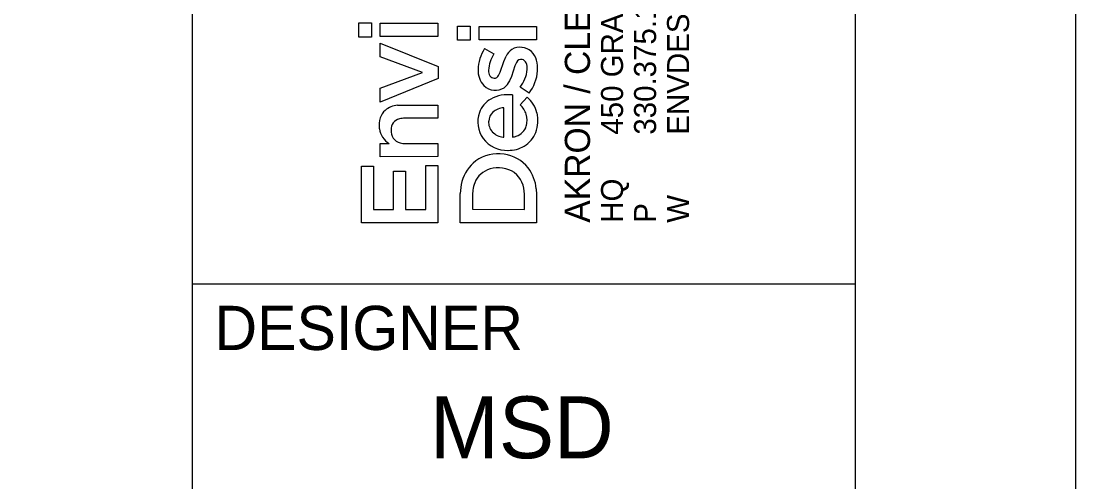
# Model space of a CAD drawing. Extents: x -4.2 to 34, y 0 to 22.
# Drawn here: x 31.612 to 34, y 2.552 to 3.594 of the extents above; entities that cross this region are included whole.
import ezdxf

# ---------------------------------------------------------------- set-up
doc = ezdxf.new("R2010")
doc.units = 0
for name, color, linetype in [('SH_Border', 7, 'Continuous'), ('SH_Cut_Line', 7, 'Continuous'), ('SH_Data', 7, 'Continuous')]:
    doc.layers.add(name, color=color, linetype=linetype)

msp = doc.modelspace()

# ---------------------------------------------------------------- linework, layer by layer
at = {"layer": 'SH_Border'}
for p, q in [((32, 0.5), (32, 21.5)), ((32, 3), (33.5, 3))]:
    msp.add_line(p, q, dxfattribs=at)
msp.add_lwpolyline([(1.5, 21.5), (33.5, 21.5), (33.5, 0.5), (1.5, 0.5)], close=True, dxfattribs=at)
at = {"layer": 'SH_Cut_Line'}
msp.add_lwpolyline([(0, 0), (34, 0), (34, 22), (0, 22)], close=True, dxfattribs=at)
at = {"layer": 'SH_Data'}
for p, q in [((32.3771, 3.5582), (32.3771, 3.5903)), ((32.3771, 3.5903), (32.4054, 3.5903)), ((32.4054, 3.5903), (32.4054, 3.5582)), ((32.4254, 3.5594), (32.4254, 3.5893)), ((32.4254, 3.5893), (32.5557, 3.5893)), ((32.5557, 3.5893), (32.5557, 3.5594)), ((32.6005, 3.5511), (32.6005, 3.5832)), ((32.6005, 3.5832), (32.6289, 3.5832)), ((32.6289, 3.5832), (32.6289, 3.5511)), ((32.6489, 3.5523), (32.6489, 3.5822)), ((32.6489, 3.5822), (32.7792, 3.5822)), ((32.7792, 3.5822), (32.7792, 3.5523)), ((32.4054, 3.5582), (32.3771, 3.5582)), ((32.5557, 3.5594), (32.4254, 3.5594)), ((32.4254, 3.5133), (32.4254, 3.5446)), ((32.4254, 3.5446), (32.5567, 3.4913)), ((32.6289, 3.5511), (32.6005, 3.5511)), ((32.7792, 3.5523), (32.6489, 3.5523)), ((32.5212, 3.478), (32.4254, 3.5133)), ((32.6615, 3.5321), (32.6827, 3.5203)), ((32.7048, 3.5026), (32.7104, 3.5153)), ((32.5567, 3.4913), (32.5567, 3.4644)), ((32.6967, 3.4787), (32.7048, 3.5026)), ((32.7298, 3.4933), (32.7221, 3.4688)), ((32.7334, 3.501), (32.7298, 3.4933)), ((32.4254, 3.4429), (32.5212, 3.478)), ((32.5567, 3.4644), (32.4254, 3.4109)), ((32.693, 3.4712), (32.6967, 3.4787)), ((32.7221, 3.4688), (32.7182, 3.4592)), ((32.4254, 3.4109), (32.4254, 3.4429)), ((32.7621, 3.4314), (32.742, 3.4447)), ((32.7245, 3.4275), (32.7246, 3.3319)), ((32.7423, 3.4046), (32.7577, 3.422)), ((32.4644, 3.404), (32.4729, 3.4044)), ((32.4729, 3.4044), (32.5557, 3.4044)), ((32.5557, 3.4044), (32.5557, 3.3746)), ((32.7049, 3.3318), (32.7049, 3.3983)), ((32.5557, 3.3746), (32.4814, 3.3746)), ((32.7036, 3.3317), (32.7049, 3.3318)), ((32.4254, 3.2875), (32.4254, 3.3173)), ((32.4254, 3.3173), (32.4455, 3.3173)), ((32.4822, 3.3173), (32.5557, 3.3173)), ((32.5557, 3.3173), (32.5557, 3.2876)), ((32.5557, 3.2876), (32.4254, 3.2875)), ((32.383, 3.1379), (32.383, 3.266)), ((32.383, 3.266), (32.4101, 3.266)), ((32.4101, 3.266), (32.4101, 3.1683)), ((32.455, 3.1683), (32.455, 3.2549)), ((32.455, 3.2549), (32.4822, 3.2549)), ((32.4822, 3.2549), (32.4822, 3.1683)), ((32.5286, 3.1683), (32.5286, 3.2672)), ((32.5286, 3.2672), (32.5557, 3.2672)), ((32.5557, 3.2672), (32.5557, 3.1379)), ((32.6064, 3.138), (32.6064, 3.204)), ((32.6347, 3.2118), (32.6341, 3.2023)), ((32.6341, 3.2023), (32.6341, 3.1684)), ((32.7515, 3.1683), (32.7515, 3.2024)), ((32.7785, 3.215), (32.7792, 3.2021)), ((32.7792, 3.2021), (32.7792, 3.138)), ((32.4101, 3.1683), (32.455, 3.1683)), ((32.4822, 3.1683), (32.5286, 3.1683)), ((32.6341, 3.1684), (32.7515, 3.1683)), ((32.5557, 3.1379), (32.383, 3.1379)), ((32.7792, 3.138), (32.6064, 3.138))]:
    msp.add_line(p, q, dxfattribs=at)
for points in [[(32.3771, 3.5582), (32.3771, 3.5903), (32.4054, 3.5903), (32.4054, 3.5582)], [(32.4254, 3.5594), (32.4254, 3.5893), (32.5557, 3.5893), (32.5557, 3.5594)], [(32.6005, 3.5511), (32.6005, 3.5832), (32.6289, 3.5832), (32.6289, 3.5511)], [(32.6489, 3.5523), (32.6489, 3.5822), (32.7792, 3.5822), (32.7792, 3.5523)], [(32.4254, 3.4109), (32.4254, 3.4429), (32.5212, 3.478), (32.4254, 3.5133), (32.4254, 3.5446), (32.5567, 3.4913), (32.5567, 3.4644)], [(32.383, 3.1379), (32.383, 3.266), (32.4101, 3.266), (32.4101, 3.1683), (32.455, 3.1683), (32.455, 3.2549), (32.4822, 3.2549), (32.4822, 3.1683), (32.5286, 3.1683), (32.5286, 3.2672), (32.5557, 3.2672), (32.5557, 3.1379)]]:
    msp.add_lwpolyline(points, close=True, dxfattribs=at)
for points in [[(32.6615, 3.5321), (32.6827, 3.5203)], [(32.693, 3.4712), (32.6967, 3.4787), (32.7048, 3.5026), (32.7104, 3.5153)], [(32.7334, 3.501), (32.7298, 3.4933), (32.7221, 3.4688), (32.7182, 3.4592)], [(32.7621, 3.4314), (32.742, 3.4447)], [(32.7245, 3.4275), (32.7246, 3.3319)], [(32.7423, 3.4046), (32.7577, 3.422)], [(32.4644, 3.404), (32.4729, 3.4044), (32.5557, 3.4044), (32.5557, 3.3746), (32.4814, 3.3746)], [(32.7036, 3.3317), (32.7049, 3.3318), (32.7049, 3.3983)], [(32.4254, 3.2875), (32.4254, 3.3173), (32.4455, 3.3173)], [(32.4822, 3.3173), (32.5557, 3.3173), (32.5557, 3.2876), (32.4254, 3.2875)], [(32.7785, 3.215), (32.7792, 3.2021), (32.7792, 3.138), (32.6064, 3.138)], [(32.6064, 3.138), (32.6064, 3.204)], [(32.6347, 3.2118), (32.6341, 3.2023), (32.6341, 3.1684), (32.7515, 3.1683), (32.7515, 3.2024)]]:
    msp.add_lwpolyline(points, dxfattribs=at)
for centre, radius, start, end in [((32.7406, 3.5026), 0.0326, 80.1719, 122.5197), ((32.7406, 3.5026), 0.0326, 80.1719, 122.5197), ((32.7428, 3.4982), 0.0367, 47.7934, 84.6892), ((32.7428, 3.4982), 0.0367, 47.7934, 84.6892), ((32.7364, 3.4826), 0.0897, 146.531, 178.7571), ((32.7364, 3.4826), 0.0897, 146.531, 178.7571), ((32.7452, 3.4789), 0.0749, 146.5112, 176.9101), ((32.7452, 3.4789), 0.0749, 146.5112, 176.9101), ((32.7466, 3.4971), 0.0405, 125.5118, 153.4159), ((32.7466, 3.4971), 0.0405, 125.5118, 153.4159), ((32.7379, 3.4946), 0.0427, 14.9966, 46.2063), ((32.7379, 3.4946), 0.0427, 14.9966, 46.2063), ((32.7438, 3.4963), 0.0114, 76.6609, 155.7053), ((32.7438, 3.4963), 0.0114, 76.6609, 155.7053), ((32.744, 3.4951), 0.0126, 21.5098, 78.5262), ((32.744, 3.4951), 0.0126, 21.5098, 78.5262), ((32.7259, 3.4877), 0.0321, 354.5726, 22.068), ((32.7259, 3.4877), 0.0321, 354.5726, 22.068), ((32.7104, 3.4867), 0.0712, 355.8306, 15.3914), ((32.7104, 3.4867), 0.0712, 355.8306, 15.3914), ((32.6967, 3.4824), 0.0501, 177.5366, 222.7932), ((32.6967, 3.4824), 0.0501, 177.5366, 222.7932), ((32.6931, 3.4823), 0.0228, 178.4747, 211.0868), ((32.6931, 3.4823), 0.0228, 178.4747, 211.0868), ((32.6833, 3.4767), 0.0115, 212.2368, 268.3777), ((32.6833, 3.4767), 0.0115, 212.2368, 268.3777), ((32.6834, 3.4759), 0.0107, 267.716, 333.7337), ((32.6834, 3.4759), 0.0107, 267.716, 333.7337), ((32.6825, 3.4915), 0.0757, 321.811, 354.7969), ((32.6825, 3.4915), 0.0757, 321.811, 354.7969), ((32.6895, 3.4882), 0.0922, 321.9777, 355.8738), ((32.6895, 3.4882), 0.0922, 321.9777, 355.8738), ((32.686, 3.4753), 0.0375, 225.9854, 302.4797), ((32.686, 3.4753), 0.0375, 225.9854, 302.4797), ((32.681, 3.4758), 0.0408, 308.0877, 335.9874), ((32.681, 3.4758), 0.0408, 308.0877, 335.9874), ((32.7024, 3.3691), 0.0558, 118.8308, 160.6244), ((32.7024, 3.3691), 0.0558, 118.8308, 160.6244), ((32.7152, 3.3441), 0.0838, 83.615, 118.2876), ((32.7152, 3.3441), 0.0838, 83.615, 118.2876), ((32.7174, 3.3717), 0.0644, 13.5336, 51.3615), ((32.7174, 3.3717), 0.0644, 13.5336, 51.3615), ((32.4635, 3.3626), 0.0402, 132.2219, 161.6818), ((32.4635, 3.3626), 0.0402, 132.2219, 161.6818), ((32.4687, 3.3543), 0.0499, 94.9696, 130.2225), ((32.4687, 3.3543), 0.0499, 94.9696, 130.2225), ((32.7079, 3.3561), 0.0424, 94.008, 130.8817), ((32.7079, 3.3561), 0.0424, 94.008, 130.8817), ((32.7038, 3.3656), 0.0549, 19.0357, 45.4406), ((32.7038, 3.3656), 0.0549, 19.0357, 45.4406), ((32.4787, 3.3582), 0.056, 162.2736, 187.7919), ((32.4787, 3.3582), 0.056, 162.2736, 187.7919), ((32.4748, 3.3487), 0.025, 103.6865, 182.2187), ((32.4748, 3.3487), 0.025, 103.6865, 182.2187), ((32.4811, 3.3286), 0.046, 89.6049, 105.3284), ((32.4811, 3.3286), 0.046, 89.6049, 105.3284), ((32.7104, 3.3661), 0.0644, 160.5201, 215.7831), ((32.7104, 3.3661), 0.0644, 160.5201, 215.7831), ((32.7017, 3.365), 0.0311, 175.0013, 223.283), ((32.7017, 3.365), 0.0311, 175.0013, 223.283), ((32.7005, 3.3663), 0.0298, 132.9851, 177.179), ((32.7005, 3.3663), 0.0298, 132.9851, 177.179), ((32.7107, 3.3697), 0.047, 344.6059, 17.007), ((32.7107, 3.3697), 0.047, 344.6059, 17.007), ((32.7064, 3.3692), 0.0758, 339.3542, 13.3785), ((32.7064, 3.3692), 0.0758, 339.3542, 13.3785), ((32.4703, 3.358), 0.0476, 188.962, 238.7037), ((32.4703, 3.358), 0.0476, 188.962, 238.7037), ((32.4773, 3.3456), 0.0276, 175.5854, 255.1439), ((32.4773, 3.3456), 0.0276, 175.5854, 255.1439), ((32.7089, 3.3736), 0.0423, 225.0619, 262.7974), ((32.7089, 3.3736), 0.0423, 225.0619, 262.7974), ((32.7224, 3.3671), 0.035, 288.0077, 343.5508), ((32.7224, 3.3671), 0.035, 288.0077, 343.5508), ((32.4818, 3.3595), 0.0422, 254.0916, 270.5284), ((32.4818, 3.3595), 0.0422, 254.0916, 270.5284), ((32.7125, 3.3705), 0.0687, 217.7452, 271.6543), ((32.7125, 3.3705), 0.0687, 217.7452, 271.6543), ((32.7247, 3.3522), 0.0202, 269.7003, 294.8711), ((32.7247, 3.3522), 0.0202, 269.7003, 294.8711), ((32.7189, 3.3652), 0.0626, 300.9427, 338.7323), ((32.7189, 3.3652), 0.0626, 300.9427, 338.7323), ((32.7155, 3.3724), 0.0706, 269.2048, 300.3341), ((32.7155, 3.3724), 0.0706, 269.2048, 300.3341), ((32.6939, 3.2089), 0.0865, 127.2362, 165.148), ((32.6939, 3.2089), 0.0865, 127.2362, 165.148), ((32.6923, 3.2079), 0.0864, 81.194, 125.9984), ((32.6923, 3.2079), 0.0864, 81.194, 125.9984), ((32.6946, 3.2113), 0.0827, 37.8521, 82.402), ((32.6946, 3.2113), 0.0827, 37.8521, 82.402), ((32.6889, 3.2078), 0.054, 106.1881, 157.3861), ((32.6889, 3.2078), 0.054, 106.1881, 157.3861), ((32.6928, 3.1986), 0.0639, 55.6727, 107.2093), ((32.6928, 3.1986), 0.0639, 55.6727, 107.2093), ((32.6929, 3.205), 0.0587, 357.4662, 52.2665), ((32.6929, 3.205), 0.0587, 357.4662, 52.2665), ((32.6859, 3.2057), 0.0931, 5.7333, 37.304), ((32.6859, 3.2057), 0.0931, 5.7333, 37.304), ((32.7143, 3.2028), 0.1078, 164.7861, 179.3704), ((32.7143, 3.2028), 0.1078, 164.7861, 179.3704), ((32.6983, 3.2039), 0.0641, 157.3571, 172.9275), ((32.6983, 3.2039), 0.0641, 157.3571, 172.9275)]:
    msp.add_arc(centre, radius, start, end, dxfattribs=at)

# ---------------------------------------------------------------- texts
for s, height, p in [('450 GRANT ST., AKRON, OH  44311', 0.049846, (32.9749, 3.3374)), ('AKRON / CLEVELAND / COLUMBUS', 0.056969, (32.9001, 3.138)), ('ENVDESIGNGROUP.COM', 0.049846, (33.1244, 3.3374)), ('330.375.1390', 0.049846, (33.0497, 3.3374)), ('HQ ', 0.04985, (32.9749, 3.138)), ('W', 0.0498, (33.1244, 3.138)), ('P', 0.0498, (33.0497, 3.138))]:
    msp.add_text(s, height=height, rotation=90, dxfattribs=at).set_placement(p)
for s, height, p in [('DESIGNER', 0.1, (32.05, 2.85)), ('MSD', 0.14, (32.5379, 2.605))]:
    msp.add_text(s, height=height, dxfattribs=at).set_placement(p)

doc.saveas('drawing.dxf')
